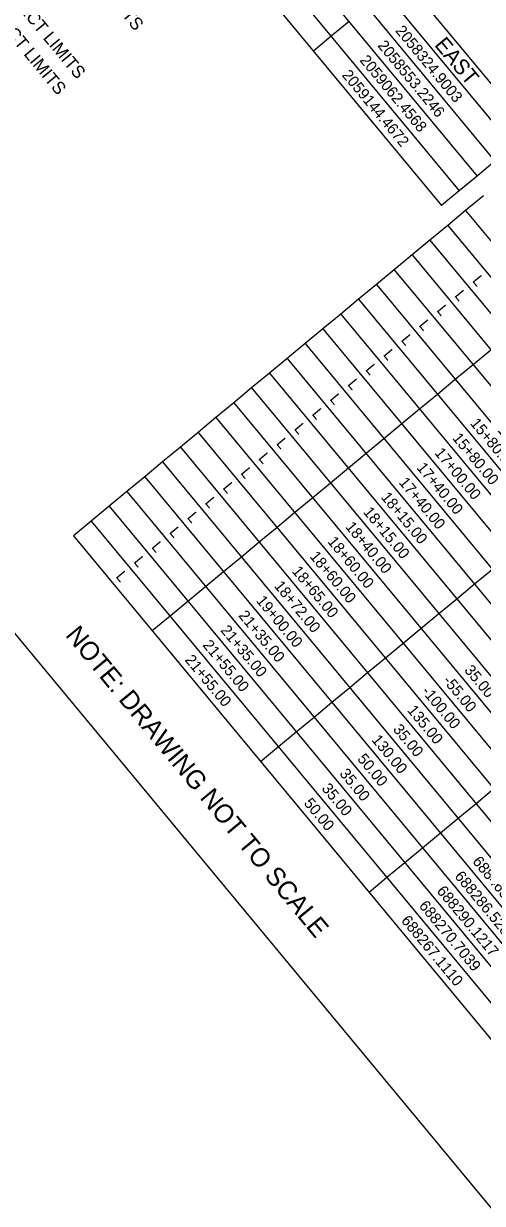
# Model space of a CAD drawing. Extents: x 2057130 to 2060012, y 687175 to 689912.
# Drawn here: x 2057863 to 2058231, y 687802 to 688749 of the extents above; entities that cross this region are included whole.
import ezdxf

# ---------------------------------------------------------------- set-up
doc = ezdxf.new("R2010")
doc.units = 0
for name, color, linetype in [('CTL Sheet Border CELL', 7, 'Continuous'), ('CTL Sheet Notes CELL', 7, 'Continuous'), ('CTL Sheet Table Cell', 7, 'Continuous'), ('CTL Sheet Text', 7, 'Continuous')]:
    doc.layers.add(name, color=color, linetype=linetype)

msp = doc.modelspace()

# ---------------------------------------------------------------- linework, layer by layer
at = {"layer": 'CTL Sheet Border CELL'}
msp.add_lwpolyline([(2059967.32, 688179.94), (2058531.08, 689911.91), (2057318.71, 688906.55), (2058754.95, 687174.58)], close=True, dxfattribs=at)
at = {"layer": 'CTL Sheet Table Cell'}
for p, q in [((2057937.41, 689063.15), (2058269.88, 688662.23)), ((2057923.09, 689051.28), (2058255.56, 688650.35)), ((2057908.77, 689039.4), (2058241.24, 688638.48)), ((2057894.46, 689027.53), (2058226.92, 688626.61)), ((2057880.14, 689015.66), (2058212.6, 688614.73)), ((2057865.82, 689003.78), (2058198.28, 688602.86)), ((2058124.01, 688750.7), (2058109.7, 688738.83)), ((2058109.7, 688738.83), (2058095.38, 688726.95)), ((2058241.24, 688638.48), (2058226.92, 688626.61)), ((2058226.92, 688626.61), (2058212.6, 688614.73)), ((2058212.6, 688614.73), (2058198.28, 688602.86)), ((2058231.95, 688610.75), (2058217.63, 688598.87)), ((2058217.63, 688598.87), (2058203.32, 688587)), ((2058217.63, 688598.87), (2058660.92, 688064.31)), ((2058203.32, 688587), (2058189, 688575.13)), ((2058203.32, 688587), (2058646.6, 688052.44)), ((2058189, 688575.13), (2058174.68, 688563.25)), ((2058189, 688575.13), (2058632.28, 688040.56)), ((2058174.68, 688563.25), (2058160.36, 688551.38)), ((2058174.68, 688563.25), (2058617.97, 688028.69)), ((2058160.36, 688551.38), (2058146.04, 688539.51)), ((2058160.36, 688551.38), (2058603.65, 688016.81)), ((2058146.04, 688539.51), (2058131.72, 688527.63)), ((2058146.04, 688539.51), (2058589.33, 688004.94)), ((2058131.72, 688527.63), (2058117.4, 688515.76)), ((2058131.72, 688527.63), (2058575.01, 687993.07)), ((2058117.4, 688515.76), (2058103.08, 688503.88)), ((2058117.4, 688515.76), (2058560.69, 687981.19)), ((2058103.08, 688503.88), (2058088.77, 688492.01)), ((2058103.08, 688503.88), (2058546.37, 687969.32)), ((2058088.77, 688492.01), (2058074.45, 688480.14)), ((2058088.77, 688492.01), (2058532.05, 687957.45)), ((2058238, 688486.89), (2058223.69, 688475.01)), ((2058074.45, 688480.14), (2058060.13, 688468.26)), ((2058074.45, 688480.14), (2058517.73, 687945.57)), ((2058223.69, 688475.01), (2058209.37, 688463.14)), ((2058060.13, 688468.26), (2058045.81, 688456.39)), ((2058060.13, 688468.26), (2058503.42, 687933.7)), ((2058045.81, 688456.39), (2058031.49, 688444.52)), ((2058045.81, 688456.39), (2058489.1, 687921.82)), ((2058209.37, 688463.14), (2058195.05, 688451.27)), ((2058195.05, 688451.27), (2058180.73, 688439.39)), ((2058031.49, 688444.52), (2058017.17, 688432.64)), ((2058031.49, 688444.52), (2058474.78, 687909.95)), ((2058031.49, 688444.52), (2058474.78, 687909.95)), ((2058180.73, 688439.39), (2058166.41, 688427.52)), ((2058017.17, 688432.64), (2058002.85, 688420.77)), ((2058017.17, 688432.64), (2058460.46, 687898.08)), ((2058166.41, 688427.52), (2058152.09, 688415.64)), ((2058002.85, 688420.77), (2057988.54, 688408.89)), ((2058002.85, 688420.77), (2058446.14, 687886.2)), ((2057988.54, 688408.89), (2057974.22, 688397.02)), ((2057988.54, 688408.89), (2058431.82, 687874.33)), ((2058152.09, 688415.64), (2058137.77, 688403.77)), ((2058137.77, 688403.77), (2058123.46, 688391.9)), ((2057974.22, 688397.02), (2057959.9, 688385.15)), ((2057974.22, 688397.02), (2058417.5, 687862.46)), ((2058123.46, 688391.9), (2058109.14, 688380.02)), ((2057959.9, 688385.15), (2057945.58, 688373.27)), ((2057959.9, 688385.15), (2058403.19, 687850.58)), ((2058109.14, 688380.02), (2058094.82, 688368.15)), ((2057945.58, 688373.27), (2057931.26, 688361.4)), ((2057945.58, 688373.27), (2058388.87, 687838.71)), ((2057931.26, 688361.4), (2057916.94, 688349.53)), ((2057931.26, 688361.4), (2058374.55, 687826.83)), ((2058094.82, 688368.15), (2058080.5, 688356.28)), ((2058080.5, 688356.28), (2058066.18, 688344.4)), ((2057916.94, 688349.53), (2057902.62, 688337.65)), ((2057916.94, 688349.53), (2058360.23, 687814.96)), ((2058066.18, 688344.4), (2058051.86, 688332.53)), ((2057902.62, 688337.65), (2058345.91, 687803.09)), ((2058051.86, 688332.53), (2058037.54, 688320.65)), ((2058037.54, 688320.65), (2058023.22, 688308.78)), ((2058023.22, 688308.78), (2058008.91, 688296.91)), ((2058239.17, 688310.64), (2058224.85, 688298.77)), ((2058008.91, 688296.91), (2057994.59, 688285.03)), ((2058224.85, 688298.77), (2058210.53, 688286.89)), ((2058210.53, 688286.89), (2058196.21, 688275.02)), ((2057994.59, 688285.03), (2057980.27, 688273.16)), ((2057980.27, 688273.16), (2057965.95, 688261.29)), ((2058196.21, 688275.02), (2058181.89, 688263.15)), ((2058181.89, 688263.15), (2058167.57, 688251.27)), ((2058167.57, 688251.27), (2058153.25, 688239.4)), ((2058153.25, 688239.4), (2058138.94, 688227.52)), ((2058138.94, 688227.52), (2058124.62, 688215.65)), ((2058124.62, 688215.65), (2058110.3, 688203.78)), ((2058110.3, 688203.78), (2058095.98, 688191.9)), ((2058095.98, 688191.9), (2058081.66, 688180.03)), ((2058081.66, 688180.03), (2058067.34, 688168.16)), ((2058067.34, 688168.16), (2058053.02, 688156.28)), ((2058240.33, 688134.39), (2058226.01, 688122.52)), ((2058226.01, 688122.52), (2058211.69, 688110.65)), ((2058211.69, 688110.65), (2058197.37, 688098.77)), ((2058197.37, 688098.77), (2058183.05, 688086.9)), ((2058183.05, 688086.9), (2058168.74, 688075.03)), ((2058168.74, 688075.03), (2058154.42, 688063.15)), ((2058154.42, 688063.15), (2058140.1, 688051.28))]:
    msp.add_line(p, q, dxfattribs=at)

# ---------------------------------------------------------------- texts
at = {"layer": 'CTL Sheet Border CELL'}
msp.add_text('NOTE: DRAWING NOT TO SCALE', height=15, rotation=309.56196, dxfattribs=at).set_placement((2057895.71, 688257.66))
at = {"layer": 'CTL Sheet Notes CELL'}
msp.add_text('EAST', height=12.401, rotation=309.66721, dxfattribs=at).set_placement((2058192.09, 688731.74))
at = {"layer": 'CTL Sheet Text'}
for s, height, p in [('101    BL-101   689159.4194   2058234.9865   328.46     OUTSIDE PROJECT LIMITS                 ', 10.0934, (2057624.08, 689138.09)), ('104    BL-104   688095.7967   2059136.4005   371.82     OUTSIDE PROJECT LIMITS', 10.0934, (2057577.46, 689099.44)), ('105    BL-105   687872.8882   2059202.7996   388.43     OUTSIDE PROJECT LIMITS                 ', 10.0934, (2057561.92, 689086.55)), ('2058324.9003', 8.8578, (2058160.81, 688743.1)), ('2058553.2246', 8.8578, (2058146.49, 688731.22)), ('2059062.4568', 8.8578, (2058132.18, 688719.35)), ('2059144.4672', 8.8578, (2058117.86, 688707.48)), ('L', 8.86, (2058222.54, 688542.31)), ('L', 8.86, (2058208.22, 688530.43)), ('L', 8.86, (2058193.9, 688518.56)), ('L', 8.86, (2058179.58, 688506.69)), ('L', 8.86, (2058165.27, 688494.81)), ('L', 8.86, (2058150.95, 688482.94)), ('L', 8.86, (2058136.63, 688471.07)), ('L', 8.86, (2058122.31, 688459.19)), ('L', 8.86, (2058107.99, 688447.32)), ('L', 8.86, (2058093.67, 688435.44)), ('L', 8.86, (2058079.35, 688423.57)), ('15+80.00', 8.858, (2058220.83, 688427.81)), ('15+80.00', 8.858, (2058206.51, 688415.93)), ('L', 8.86, (2058065.03, 688411.7)), ('L', 8.86, (2058050.72, 688399.82)), ('17+00.00', 8.858, (2058192.2, 688404.06)), ('L', 8.86, (2058036.4, 688387.95)), ('17+40.00', 8.858, (2058177.88, 688392.18)), ('L', 8.86, (2058022.08, 688376.08)), ('17+40.00', 8.858, (2058163.56, 688380.31)), ('18+15.00', 8.858, (2058149.24, 688368.44)), ('L', 8.86, (2058007.76, 688364.2)), ('L', 8.86, (2057993.44, 688352.33)), ('18+15.00', 8.858, (2058134.92, 688356.56)), ('L', 8.86, (2057979.12, 688340.45)), ('18+40.00', 8.858, (2058120.6, 688344.69)), ('L', 8.86, (2057964.8, 688328.58)), ('18+60.00', 8.858, (2058106.28, 688332.81)), ('18+60.00', 8.858, (2058091.96, 688320.94)), ('L', 8.86, (2057950.49, 688316.71)), ('L', 8.86, (2057936.17, 688304.83)), ('18+65.00', 8.858, (2058077.65, 688309.07)), ('18+72.00', 8.858, (2058063.33, 688297.19)), ('19+00.00', 8.858, (2058049.01, 688285.32)), ('21+35.00', 8.858, (2058034.69, 688273.45)), ('21+35.00', 8.858, (2058020.37, 688261.57)), ('21+55.00', 8.858, (2058006.05, 688249.7)), ('21+55.00', 8.858, (2057991.73, 688237.82)), ('35.00', 8.858, (2058216.09, 688229.54)), ('-55.00', 8.858, (2058198.97, 688221.05)), ('-100.00', 8.858, (2058181.84, 688212.56)), ('135.00', 8.858, (2058170.33, 688197.3)), ('35.00', 8.858, (2058158.82, 688182.04)), ('130.00', 8.858, (2058141.69, 688173.55)), ('50.00', 8.858, (2058130.18, 688158.3)), ('35.00', 8.858, (2058115.86, 688146.42)), ('35.00', 8.858, (2058101.54, 688134.55)), ('50.00', 8.858, (2058087.22, 688122.67)), ('688463.8072', 8.8578, (2058222.66, 688075.91)), ('688286.5288', 8.8578, (2058208.34, 688064.04)), ('688290.1217', 8.8578, (2058194.02, 688052.17)), ('688270.7039', 8.8578, (2058179.7, 688040.29)), ('688267.1110', 8.8578, (2058165.38, 688028.42))]:
    msp.add_text(s, height=height, rotation=309.66721, dxfattribs=at).set_placement(p)

doc.saveas('drawing.dxf')
